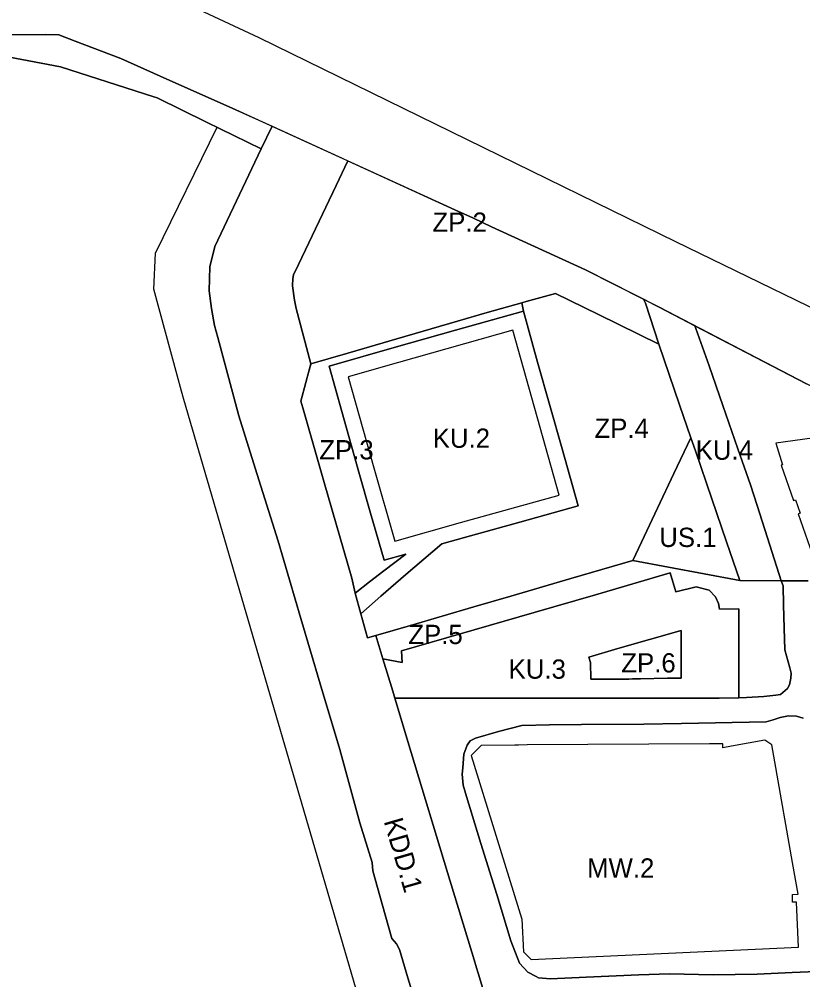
# Model space of a CAD drawing. Extents: x 7429178 to 7430831, y 5550228 to 5551611.
# Drawn here: x 7429876.2 to 7430079.5, y 5551215.2 to 5551464.4 of the extents above; entities that cross this region are included whole.
import ezdxf

# ---------------------------------------------------------------- set-up
doc = ezdxf.new("R2010")
doc.units = 0
for name, color, linetype in [('linie rozgraniczające', 7, 'Continuous'), ('nieprzekraczalne linie zabudowy', 7, 'Continuous'), ('obowiazujace linie zabudowy', 7, 'Continuous'), ('przeznaczenia terenów', 7, 'Continuous')]:
    doc.layers.add(name, color=color, linetype=linetype)

msp = doc.modelspace()

# ---------------------------------------------------------------- linework, layer by layer
at = {"layer": 'linie rozgraniczające'}
for points in [[(7429869.41, 5551487.14), (7429893.85, 5551479.52), (7429909.85, 5551473.11), (7429938.37, 5551459.65), (7430046.47, 5551406.73), (7430099.49, 5551380.97), (7430204.21, 5551330.07), (7430283.32, 5551292.27)], [(7429872.08, 5551460.34), (7429882.93, 5551460.46), (7429886.5, 5551460.38), (7429890.71, 5551458.71), (7429902.53, 5551454.19), (7429912.77, 5551449.66), (7429932.38, 5551440.93), (7429941.8, 5551436.64), (7429939, 5551430.76), (7429924.79, 5551437.74), (7429911.98, 5551444.03), (7429911.11, 5551444.31), (7429886.86, 5551452.09), (7429876.86, 5551453.97), (7429859.94, 5551457.16)], [(7430247.95, 5551286.58), (7430223.25, 5551298.98), (7430220.66, 5551300.21), (7430209.78, 5551305.52), (7430196.74, 5551311.87), (7430180.61, 5551319.73), (7430138.22, 5551340.73), (7430134.15, 5551342.78), (7430093.77, 5551363.12), (7430080.47, 5551369.78), (7430042.2, 5551389.71), (7430023.15, 5551399.37), (7429998.77, 5551410.53), (7429994.07, 5551412.83), (7429989.24, 5551414.99), (7429932.38, 5551440.93), (7429912.77, 5551449.66), (7429902.53, 5551454.19), (7429890.71, 5551458.71), (7429886.5, 5551460.38), (7429882.93, 5551460.46), (7429872.08, 5551460.34)], [(7429859.94, 5551457.16), (7429876.86, 5551453.97), (7429886.86, 5551452.09), (7429911.11, 5551444.31), (7429911.98, 5551444.03), (7429924.79, 5551437.74), (7429939, 5551430.76), (7429926.94, 5551405.42), (7429925.62, 5551400.2), (7429925.43, 5551393.98), (7429926.1, 5551389.38), (7429926.84, 5551384.94), (7429927.69, 5551381.81), (7429933.21, 5551361.52), (7429937.41, 5551347.9), (7429943.39, 5551328.96), (7429949.26, 5551308.9), (7429954.27, 5551291.96), (7429959.42, 5551274.95), (7429964.53, 5551255.92), (7429967.75, 5551245.59), (7429967.9, 5551243.46), (7429970.37, 5551234.82), (7429972.91, 5551225.94), (7429974.12, 5551224.51), (7429974.82, 5551223.08), (7429977.04, 5551215.75), (7429981.74, 5551200.32)], [(7429981.74, 5551200.32), (7429977.04, 5551215.75), (7429974.82, 5551223.08), (7429974.12, 5551224.51), (7429972.91, 5551225.94), (7429970.37, 5551234.82), (7429967.9, 5551243.46), (7429967.75, 5551245.59), (7429964.53, 5551255.92), (7429959.42, 5551274.95), (7429954.27, 5551291.96), (7429949.26, 5551308.9), (7429943.39, 5551328.96), (7429937.41, 5551347.9), (7429933.21, 5551361.52), (7429927.69, 5551381.81), (7429926.84, 5551384.94), (7429926.1, 5551389.38), (7429925.43, 5551393.98), (7429925.62, 5551400.2), (7429926.94, 5551405.42), (7429939, 5551430.76), (7429941.8, 5551436.64), (7429959.99, 5551428.33), (7429961.45, 5551427.67), (7429958.39, 5551421.24), (7429948.66, 5551400.8), (7429947.36, 5551398.07), (7429947.14, 5551397.18), (7429947.08, 5551395.23), (7429947.63, 5551391.49), (7429948.03, 5551389.33), (7429951.82, 5551374.99), (7429951.88, 5551374.96), (7429950.99, 5551371.79), (7429950.55, 5551370.2), (7429949.26, 5551365.33), (7429949.78, 5551363.59), (7429955.27, 5551344.25), (7429962.51, 5551319.4), (7429963.35, 5551315.51), (7429964.81, 5551310.17), (7429966.53, 5551303.9), (7429968.75, 5551304.51), (7429970.57, 5551298.5), (7429973.13, 5551290.04), (7429973.67, 5551288.24), (7429977.93, 5551274.21), (7429987.36, 5551243.03), (7429994.22, 5551220.34), (7429994.84, 5551218.28), (7429995.24, 5551216.96), (7429997.85, 5551208.32)], [(7430080.95, 5551318.71), (7430073.94, 5551318.73), (7430070.97, 5551327.96), (7430067.65, 5551338.26), (7430065.91, 5551343.58), (7430062.66, 5551352.93), (7430058.73, 5551364.24), (7430055.18, 5551374.53), (7430051.76, 5551384.15), (7430051.51, 5551384.86), (7430080.47, 5551369.78)], [(7429997.85, 5551208.32), (7429995.24, 5551216.96), (7429994.84, 5551218.28), (7429994.22, 5551220.34), (7429987.36, 5551243.03), (7429977.93, 5551274.21), (7429973.67, 5551288.24), (7430019.06, 5551288.28), (7430030.81, 5551288.29), (7430045.38, 5551288.3), (7430048.02, 5551288.3), (7430057.84, 5551288.31), (7430062.88, 5551288.39), (7430064.87, 5551288.42), (7430069.38, 5551288.72), (7430072.52, 5551289.03), (7430073.69, 5551289.24), (7430075.51, 5551290.8), (7430076.1, 5551291.75), (7430076.42, 5551293.44), (7430076.47, 5551294.77), (7430076.18, 5551296.17), (7430075.31, 5551299.27), (7430074.83, 5551300.85), (7430074.66, 5551306.42), (7430074.47, 5551312.46), (7430074.44, 5551317.39), (7430073.94, 5551318.73), (7430080.95, 5551318.71)], [(7430085.08, 5551217.47), (7430076.73, 5551217.09), (7430067.7, 5551216.67), (7430056.26, 5551216.47), (7430044.9, 5551216.74), (7430036.94, 5551216.49), (7430023.31, 5551215.86), (7430014.08, 5551215.43), (7430010.92, 5551215.73), (7430010.34, 5551216.04), (7430008.13, 5551217.21), (7430005.97, 5551219.54), (7430003.78, 5551225.34), (7430000.08, 5551237.3), (7429995.99, 5551250.53), (7429992.22, 5551262.74), (7429991.38, 5551265.7), (7429991.16, 5551268.57), (7429991.3, 5551270.17), (7429991.59, 5551273.75), (7429992.39, 5551276.08), (7429993.16, 5551277.16), (7429994.56, 5551277.87), (7430000.59, 5551279.59), (7430006.57, 5551281.18), (7430013.8, 5551281.31), (7430022.1, 5551281.4), (7430038.26, 5551281.49), (7430048.06, 5551281.73), (7430069.99, 5551282.13), (7430071.79, 5551282.68), (7430073.61, 5551283.22), (7430075.78, 5551283.65), (7430077.9, 5551283.59), (7430079.64, 5551283.07)], [(7430079.64, 5551283.07), (7430077.9, 5551283.59), (7430075.78, 5551283.65), (7430073.61, 5551283.22), (7430071.79, 5551282.68), (7430069.99, 5551282.13), (7430048.06, 5551281.73), (7430038.26, 5551281.49), (7430022.1, 5551281.4), (7430013.8, 5551281.31), (7430006.57, 5551281.18), (7430000.59, 5551279.59), (7429994.56, 5551277.87), (7429993.16, 5551277.16), (7429992.39, 5551276.08), (7429991.59, 5551273.75), (7429991.3, 5551270.17), (7429991.16, 5551268.57), (7429991.38, 5551265.7), (7429992.22, 5551262.74), (7429995.99, 5551250.53), (7430000.08, 5551237.3), (7430003.78, 5551225.34), (7430005.97, 5551219.54), (7430008.13, 5551217.21), (7430010.34, 5551216.04), (7430010.92, 5551215.73), (7430014.08, 5551215.43), (7430023.31, 5551215.86), (7430036.94, 5551216.49), (7430044.9, 5551216.74), (7430056.26, 5551216.47), (7430067.7, 5551216.67), (7430076.73, 5551217.09), (7430085.08, 5551217.47)]]:
    msp.add_lwpolyline(points, dxfattribs=at)
for points in [[(7430023.15, 5551399.37), (7430038.16, 5551391.76), (7430038.67, 5551390.71), (7430042.15, 5551380.09), (7430026.47, 5551387.8), (7430015.38, 5551393.25), (7430007.75, 5551391.14), (7430006.57, 5551390.81), (7429997.63, 5551388.33), (7429989.87, 5551386.11), (7429974.13, 5551381.47), (7429961.46, 5551377.79), (7429951.89, 5551375.01), (7429951.88, 5551374.96), (7429951.82, 5551374.99), (7429948.03, 5551389.33), (7429947.63, 5551391.49), (7429947.08, 5551395.23), (7429947.14, 5551397.18), (7429947.36, 5551398.07), (7429948.66, 5551400.8), (7429958.39, 5551421.24), (7429961.45, 5551427.67), (7429989.24, 5551414.99), (7429994.07, 5551412.83), (7429998.77, 5551410.53)], [(7430007.07, 5551388.7), (7429989.35, 5551383.71), (7429973.5, 5551379.24), (7429956.63, 5551374.38), (7429959.9, 5551362.6), (7429964.31, 5551346.94), (7429967.31, 5551336.26), (7429970.86, 5551324.06), (7429976.49, 5551325.67), (7429970.83, 5551321.34), (7429967.04, 5551318.42), (7429963.35, 5551315.51), (7429962.51, 5551319.4), (7429955.27, 5551344.25), (7429949.78, 5551363.59), (7429949.26, 5551365.33), (7429950.55, 5551370.2), (7429951.89, 5551375.01), (7429961.46, 5551377.79), (7429974.13, 5551381.47), (7429989.87, 5551386.11), (7429997.63, 5551388.33), (7430006.57, 5551390.81)], [(7430042.15, 5551380.09), (7430047.53, 5551364.38), (7430050.45, 5551355.84), (7430050.45, 5551355.84), (7430046.07, 5551346.56), (7430041.81, 5551337.54), (7430037.64, 5551328.71), (7430035.42, 5551324.01), (7430019.3, 5551319.3), (7430003.78, 5551314.76), (7429994.13, 5551311.93), (7429977.75, 5551307.14), (7429968.75, 5551304.51), (7429966.53, 5551303.9), (7429964.81, 5551310.17), (7429969.98, 5551314.7), (7429976.53, 5551320.37), (7429985.84, 5551328.35), (7429991.77, 5551329.98), (7430006.12, 5551333.95), (7430021.23, 5551338.15), (7430017.04, 5551352.93), (7430010.71, 5551375.42), (7430007.07, 5551388.7), (7430006.57, 5551390.81), (7430007.75, 5551391.14), (7430015.38, 5551393.25), (7430026.47, 5551387.8)], [(7430070.97, 5551327.96), (7430073.94, 5551318.73), (7430063.14, 5551318.76), (7430059.71, 5551328.79), (7430055.89, 5551339.95), (7430051.63, 5551352.4), (7430050.45, 5551355.84), (7430047.53, 5551364.38), (7430042.15, 5551380.09), (7430038.67, 5551390.71), (7430038.16, 5551391.76), (7430042.2, 5551389.71), (7430051.51, 5551384.86), (7430051.76, 5551384.15), (7430055.18, 5551374.53), (7430058.73, 5551364.24), (7430062.66, 5551352.93), (7430065.91, 5551343.58), (7430067.65, 5551338.26)], [(7429964.81, 5551310.17), (7429963.35, 5551315.51), (7429967.04, 5551318.42), (7429970.83, 5551321.34), (7429976.49, 5551325.67), (7429970.86, 5551324.06), (7429967.31, 5551336.26), (7429964.31, 5551346.94), (7429959.9, 5551362.6), (7429956.63, 5551374.38), (7429973.5, 5551379.24), (7429989.35, 5551383.71), (7430007.07, 5551388.7), (7430010.71, 5551375.42), (7430017.04, 5551352.93), (7430021.23, 5551338.15), (7430006.12, 5551333.95), (7429991.77, 5551329.98), (7429985.84, 5551328.35), (7429976.53, 5551320.37), (7429969.98, 5551314.7)], [(7430059.71, 5551328.79), (7430063.14, 5551318.76), (7430035.42, 5551324.01), (7430037.64, 5551328.71), (7430041.81, 5551337.54), (7430046.07, 5551346.56), (7430050.45, 5551355.84), (7430050.45, 5551355.84), (7430051.63, 5551352.4), (7430055.89, 5551339.95)], [(7430062.88, 5551288.39), (7430062.95, 5551296.07), (7430062.91, 5551311.44), (7430057.87, 5551311.4), (7430057.6, 5551312.79), (7430056.84, 5551314.58), (7430055.18, 5551316.28), (7430051.86, 5551317.15), (7430046.57, 5551315.86), (7430045.1, 5551320.75), (7430025.7, 5551315.12), (7430009.81, 5551310.53), (7429975.34, 5551300.55), (7429975.53, 5551297.55), (7429970.57, 5551298.5), (7429968.75, 5551304.51), (7429977.75, 5551307.14), (7429994.13, 5551311.93), (7430003.78, 5551314.76), (7430019.3, 5551319.3), (7430035.42, 5551324.01), (7430063.14, 5551318.76), (7430073.94, 5551318.73), (7430074.44, 5551317.39), (7430074.47, 5551312.46), (7430074.66, 5551306.42), (7430074.83, 5551300.85), (7430075.31, 5551299.27), (7430076.18, 5551296.17), (7430076.47, 5551294.77), (7430076.42, 5551293.44), (7430076.1, 5551291.75), (7430075.51, 5551290.8), (7430073.69, 5551289.24), (7430072.52, 5551289.03), (7430069.38, 5551288.72), (7430064.87, 5551288.42)], [(7430062.88, 5551288.39), (7430057.84, 5551288.31), (7430048.02, 5551288.3), (7430045.38, 5551288.3), (7430030.81, 5551288.29), (7430019.06, 5551288.28), (7429973.67, 5551288.24), (7429973.13, 5551290.04), (7429970.57, 5551298.5), (7429975.53, 5551297.55), (7429975.34, 5551300.55), (7430009.81, 5551310.53), (7430025.7, 5551315.12), (7430045.1, 5551320.75), (7430046.57, 5551315.86), (7430051.86, 5551317.15), (7430055.18, 5551316.28), (7430056.84, 5551314.58), (7430057.6, 5551312.79), (7430057.87, 5551311.4), (7430062.91, 5551311.44), (7430062.95, 5551296.07)], [(7430037.43, 5551293.28), (7430044.39, 5551293.44), (7430044.39, 5551293.44), (7430044.39, 5551293.44), (7430045.18, 5551293.46), (7430047.94, 5551293.44), (7430047.94, 5551293.44), (7430047.96, 5551294.54), (7430047.96, 5551294.55), (7430047.96, 5551294.83), (7430047.97, 5551297.83), (7430047.97, 5551299.66), (7430047.97, 5551305.85), (7430031.51, 5551301.13), (7430024.01, 5551298.91), (7430024.01, 5551298.91), (7430024.44, 5551297.51), (7430024.47, 5551293.22), (7430026.39, 5551293.22), (7430027.43, 5551293.22), (7430028.23, 5551293.22), (7430028.66, 5551293.22), (7430030.06, 5551293.22), (7430031.45, 5551293.22), (7430034.35, 5551293.21), (7430035.34, 5551293.24), (7430035.54, 5551293.24)], [(7430047.96, 5551294.54), (7430047.94, 5551293.44), (7430047.94, 5551293.44), (7430045.18, 5551293.46), (7430044.39, 5551293.44), (7430044.39, 5551293.44), (7430044.39, 5551293.44), (7430037.43, 5551293.28), (7430035.54, 5551293.24), (7430035.34, 5551293.24), (7430034.35, 5551293.21), (7430031.45, 5551293.22), (7430030.06, 5551293.22), (7430028.66, 5551293.22), (7430028.23, 5551293.22), (7430027.43, 5551293.22), (7430026.39, 5551293.22), (7430024.47, 5551293.22), (7430024.44, 5551297.51), (7430024.01, 5551298.91), (7430024.01, 5551298.91), (7430031.51, 5551301.13), (7430047.97, 5551305.85), (7430047.97, 5551299.66), (7430047.97, 5551297.83), (7430047.96, 5551294.83), (7430047.96, 5551294.55)]]:
    msp.add_lwpolyline(points, close=True, dxfattribs=at)
at = {"layer": 'nieprzekraczalne linie zabudowy'}
for points in [[(7429917.17, 5551372.03), (7429911.15, 5551394.35), (7429911.58, 5551403.71), (7429927.58, 5551436.37)], [(7430016.3, 5551340.93), (7430004.3, 5551383.76), (7429974.59, 5551375.39), (7429961.55, 5551371.64), (7429968.16, 5551348.03), (7429973.61, 5551329), (7429990.69, 5551333.84), (7430016.3, 5551340.93)], [(7429989.75, 5551123.38), (7429918.87, 5551365.77), (7429918.29, 5551367.92), (7429917.17, 5551372.03)]]:
    msp.add_lwpolyline(points, dxfattribs=at)
at = {"layer": 'obowiazujace linie zabudowy'}
for points in [[(7430081.92, 5551355.76), (7430072.5, 5551354.42), (7430074.25, 5551348.82), (7430073.92, 5551348.74), (7430077.11, 5551339.54), (7430077.6, 5551339.74), (7430078.79, 5551336.29), (7430078.3, 5551336.11), (7430082.51, 5551323.99)], [(7430061.02, 5551275.81), (7430058.8, 5551275.4), (7430058.76, 5551276.46), (7430055.3, 5551276.44), (7430008.01, 5551276.12), (7430005.75, 5551276.1), (7430004.8, 5551276.09), (7429996.05, 5551276.02), (7429993.49, 5551273.41), (7430006.6, 5551230.93), (7430007.04, 5551222.43), (7430009.06, 5551220.46), (7430078.43, 5551223.7), (7430077.89, 5551235.34), (7430076.82, 5551235.3), (7430076.81, 5551237.32), (7430078.33, 5551237.38), (7430076.83, 5551245.59), (7430072.25, 5551271.72), (7430071.47, 5551276.13), (7430069.62, 5551277.4), (7430061.02, 5551275.81)]]:
    msp.add_lwpolyline(points, dxfattribs=at)

# ---------------------------------------------------------------- texts
at = {"layer": 'przeznaczenia terenów'}
for s, p in [('ZP.2', (7429983.41, 5551409.27)), ('ZP.4', (7430025.46, 5551355.8)), ('KU.2', (7429983.49, 5551353.22)), ('ZP.3', (7429954.04, 5551350.21)), ('KU.4', (7430051.72, 5551350.12)), ('US.1', (7430042.27, 5551327.49)), ('ZP.5', (7429977.15, 5551302.3)), ('ZP.6', (7430032.41, 5551294.93)), ('KU.3', (7430003.18, 5551293.31)), ('MW.2', (7430023.54, 5551241.7))]:
    msp.add_text(s, height=5, dxfattribs=at).set_placement(p)
msp.add_text('KDD.1', height=5, rotation=286.1373, dxfattribs=at).set_placement((7429970.73, 5551256.37))

doc.saveas('drawing.dxf')
